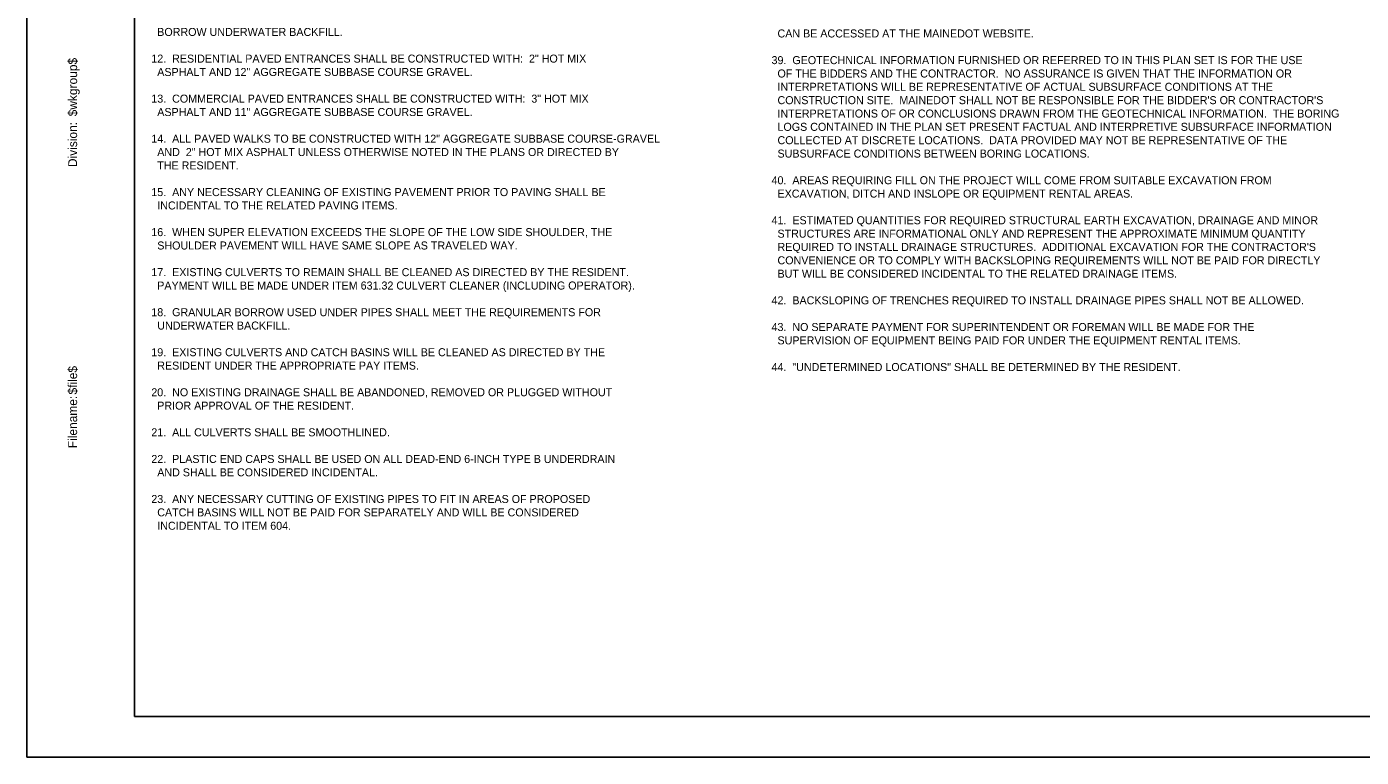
# Model space of a CAD drawing. Extents: x -0.13 to 2.7, y -0.05 to 1.78.
# Drawn here: x -0.135 to 1.533, y -0.051 to 0.861 of the extents above; entities that cross this region are included whole.
import ezdxf

# ---------------------------------------------------------------- set-up
doc = ezdxf.new("R2010")
doc.units = 0
for name, color, linetype in [('ANNOTATION', 7, 'Continuous'), ('BORDER', 7, 'Continuous'), ('PLOT BOUNDARY', 7, 'Continuous')]:
    doc.layers.add(name, color=color, linetype=linetype)

msp = doc.modelspace()

# ---------------------------------------------------------------- linework, layer by layer
at = {"layer": 'BORDER'}
for p, q in [((0, 1.75), (0, 0)), ((0, 0), (2.6667, 0))]:
    msp.add_line(p, q, dxfattribs=at)
at = {"layer": 'PLOT BOUNDARY'}
msp.add_lwpolyline([(-0.1349, -0.051), (2.6984, -0.051), (2.6984, 1.7823), (-0.1349, 1.7823)], close=True, dxfattribs=at)

# ---------------------------------------------------------------- texts
at = {"layer": 'ANNOTATION'}
for s, p in [('  BORROW UNDERWATER BACKFILL.', (0.0208, 0.8499)), ('  CAN BE ACCESSED AT THE MAINEDOT WEBSITE.', (0.7957, 0.848)), ('12.  RESIDENTIAL PAVED ENTRANCES SHALL BE CONSTRUCTED WITH:  2" HOT MIX ', (0.0208, 0.8166)), ('39.  GEOTECHNICAL INFORMATION FURNISHED OR REFERRED TO IN THIS PLAN SET IS FOR THE USE ', (0.7957, 0.8147)), ('  ASPHALT AND 12" AGGREGATE SUBBASE COURSE GRAVEL.', (0.0208, 0.7999)), ('  OF THE BIDDERS AND THE CONTRACTOR.  NO ASSURANCE IS GIVEN THAT THE INFORMATION OR ', (0.7957, 0.798)), ('  INTERPRETATIONS WILL BE REPRESENTATIVE OF ACTUAL SUBSURFACE CONDITIONS AT THE ', (0.7957, 0.7814)), ('13.  COMMERCIAL PAVED ENTRANCES SHALL BE CONSTRUCTED WITH:  3" HOT MIX ', (0.0208, 0.7666)), ("  CONSTRUCTION SITE.  MAINEDOT SHALL NOT BE RESPONSIBLE FOR THE BIDDER'S OR CONTRACTOR'S ", (0.7957, 0.7647)), ('  ASPHALT AND 11" AGGREGATE SUBBASE COURSE GRAVEL.', (0.0208, 0.7499)), ('  INTERPRETATIONS OF OR CONCLUSIONS DRAWN FROM THE GEOTECHNICAL INFORMATION.  THE BORING ', (0.7957, 0.748)), ('  LOGS CONTAINED IN THE PLAN SET PRESENT FACTUAL AND INTERPRETIVE SUBSURFACE INFORMATION ', (0.7957, 0.7314)), ('14.  ALL PAVED WALKS TO BE CONSTRUCTED WITH 12" AGGREGATE SUBBASE COURSE-GRAVEL ', (0.0208, 0.7166)), ('  COLLECTED AT DISCRETE LOCATIONS.  DATA PROVIDED MAY NOT BE REPRESENTATIVE OF THE ', (0.7957, 0.7147)), ('  AND  2" HOT MIX ASPHALT UNLESS OTHERWISE NOTED IN THE PLANS OR DIRECTED BY ', (0.0208, 0.6999)), ('  SUBSURFACE CONDITIONS BETWEEN BORING LOCATIONS.', (0.7957, 0.698)), ('  THE RESIDENT.', (0.0208, 0.6832)), ('40.  AREAS REQUIRING FILL ON THE PROJECT WILL COME FROM SUITABLE EXCAVATION FROM ', (0.7957, 0.6647)), ('15.  ANY NECESSARY CLEANING OF EXISTING PAVEMENT PRIOR TO PAVING SHALL BE ', (0.0208, 0.6499)), ('  EXCAVATION, DITCH AND INSLOPE OR EQUIPMENT RENTAL AREAS.', (0.7957, 0.648)), ('  INCIDENTAL TO THE RELATED PAVING ITEMS.', (0.0208, 0.6332)), ('41.  ESTIMATED QUANTITIES FOR REQUIRED STRUCTURAL EARTH EXCAVATION, DRAINAGE AND MINOR ', (0.7957, 0.6147)), ('16.  WHEN SUPER ELEVATION EXCEEDS THE SLOPE OF THE LOW SIDE SHOULDER, THE ', (0.0208, 0.5999)), ('  STRUCTURES ARE INFORMATIONAL ONLY AND REPRESENT THE APPROXIMATE MINIMUM QUANTITY ', (0.7957, 0.598)), ('  SHOULDER PAVEMENT WILL HAVE SAME SLOPE AS TRAVELED WAY.', (0.0208, 0.5832)), ("  REQUIRED TO INSTALL DRAINAGE STRUCTURES.  ADDITIONAL EXCAVATION FOR THE CONTRACTOR'S ", (0.7957, 0.5814)), ('  CONVENIENCE OR TO COMPLY WITH BACKSLOPING REQUIREMENTS WILL NOT BE PAID FOR DIRECTLY ', (0.7957, 0.5647)), ('17.  EXISTING CULVERTS TO REMAIN SHALL BE CLEANED AS DIRECTED BY THE RESIDENT.  ', (0.0208, 0.5499)), ('  BUT WILL BE CONSIDERED INCIDENTAL TO THE RELATED DRAINAGE ITEMS.  ', (0.7957, 0.548)), ('  PAYMENT WILL BE MADE UNDER ITEM 631.32 CULVERT CLEANER (INCLUDING OPERATOR).', (0.0208, 0.5332)), ('42.  BACKSLOPING OF TRENCHES REQUIRED TO INSTALL DRAINAGE PIPES SHALL NOT BE ALLOWED.', (0.7957, 0.5147)), ('18.  GRANULAR BORROW USED UNDER PIPES SHALL MEET THE REQUIREMENTS FOR ', (0.0208, 0.4999)), ('  UNDERWATER BACKFILL.', (0.0208, 0.4832)), ('43.  NO SEPARATE PAYMENT FOR SUPERINTENDENT OR FOREMAN WILL BE MADE FOR THE ', (0.7957, 0.4814)), ('  SUPERVISION OF EQUIPMENT BEING PAID FOR UNDER THE EQUIPMENT RENTAL ITEMS.', (0.7957, 0.4647)), ('19.  EXISTING CULVERTS AND CATCH BASINS WILL BE CLEANED AS DIRECTED BY THE ', (0.0208, 0.4499)), ('  RESIDENT UNDER THE APPROPRIATE PAY ITEMS.', (0.0208, 0.4332)), ('44.  "UNDETERMINED LOCATIONS" SHALL BE DETERMINED BY THE RESIDENT.', (0.7957, 0.4314)), ('20.  NO EXISTING DRAINAGE SHALL BE ABANDONED, REMOVED OR PLUGGED WITHOUT ', (0.0208, 0.3999)), ('  PRIOR APPROVAL OF THE RESIDENT.', (0.0208, 0.3832)), ('21.  ALL CULVERTS SHALL BE SMOOTHLINED.  ', (0.0208, 0.3499)), ('22.  PLASTIC END CAPS SHALL BE USED ON ALL DEAD-END 6-INCH TYPE B UNDERDRAIN', (0.0208, 0.3166)), ('  AND SHALL BE CONSIDERED INCIDENTAL.', (0.0208, 0.2999)), ('23.  ANY NECESSARY CUTTING OF EXISTING PIPES TO FIT IN AREAS OF PROPOSED ', (0.0208, 0.2666)), ('  CATCH BASINS WILL NOT BE PAID FOR SEPARATELY AND WILL BE CONSIDERED ', (0.0208, 0.2499)), ('  INCIDENTAL TO ITEM 604.', (0.0208, 0.2332))]:
    msp.add_text(s, height=0.01, dxfattribs=at).set_placement(p)
at = {"layer": 'BORDER'}
for s, p in [('$wkgroup$', (-0.0719, 0.7495)), ('Division:', (-0.0719, 0.6861)), ('$file$', (-0.0719, 0.4021)), ('Filename:', (-0.0719, 0.335))]:
    msp.add_text(s, height=0.01116, rotation=90, dxfattribs=at).set_placement(p)

doc.saveas('drawing.dxf')
